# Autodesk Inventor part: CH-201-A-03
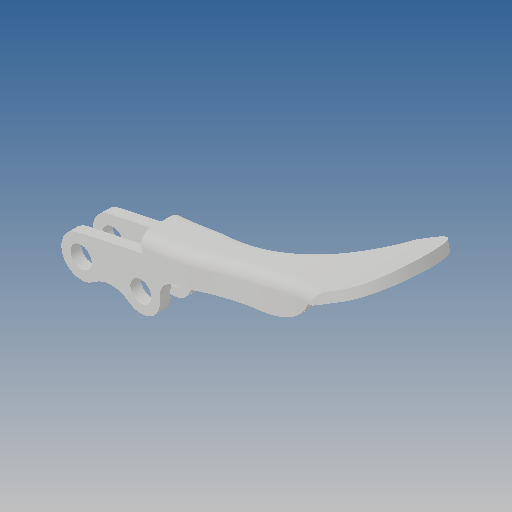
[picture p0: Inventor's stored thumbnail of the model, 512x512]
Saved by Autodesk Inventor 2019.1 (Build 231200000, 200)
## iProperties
Created: 2012-09
Part Number: CH-201-A-03
Material: Ogólny
Document SubType Name: Modeling
Designer: CADENGINEERING4
Density: 1 g/cm^3
Appearance: Domyślna
Author: CADENGINEERING4
Revision Number: ÈÎºÎ
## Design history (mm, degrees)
feature "Ô²½Ç2"
node "Bryła1"
